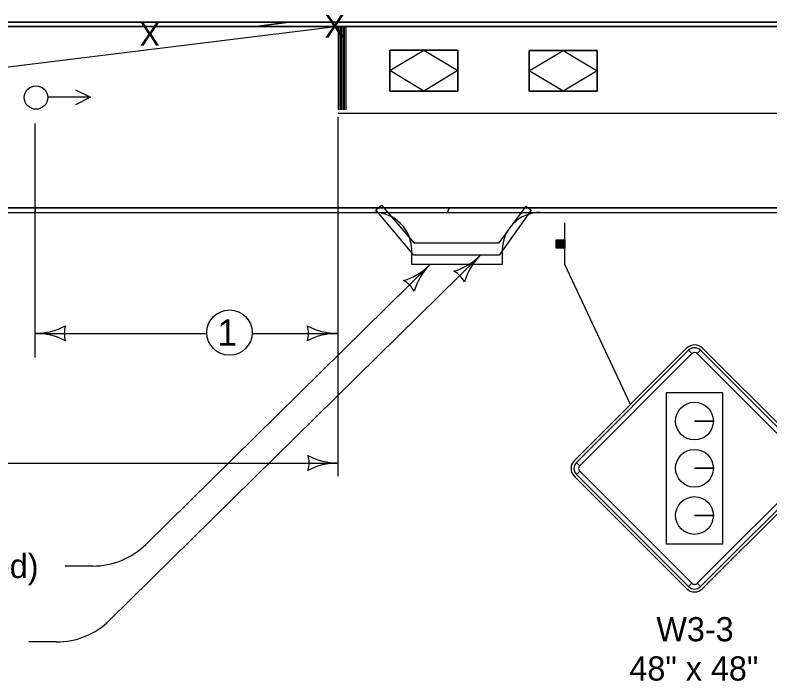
# Model space of a CAD drawing. Extents: x -2134934 to -2119606, y -2139046 to -2137036.
# Drawn here: x -2132728.3 to -2132228.7, y -2137978.4 to -2137537.5 of the extents above; entities that cross this region are included whole.
import ezdxf

# ---------------------------------------------------------------- set-up
doc = ezdxf.new("R2010")
doc.units = 0
for name, color, linetype in [('Default', 7, 'Continuous'), ('dsnCellElements', 7, 'Continuous'), ('dsnStdLabel', 7, 'Continuous'), ('dsnStdLineWork', 7, 'Continuous'), ('Level 2', 7, 'Continuous'), ('Level 4', 7, 'Continuous')]:
    doc.layers.add(name, color=color, linetype=linetype)

msp = doc.modelspace()

# ---------------------------------------------------------------- linework, layer by layer
at = {"layer": 'Default'}
for p, q in [((-2132489.5, -2137666.4), (-2132485.76, -2137663.39)), ((-2132464.31, -2137696.46), (-2132489.5, -2137666.4)), ((-2132485.76, -2137663.39), (-2132464.33, -2137688.36)), ((-2132407.87, -2137688.4), (-2132390.13, -2137664.13)), ((-2132390.13, -2137664.13), (-2132386.63, -2137666.69)), ((-2132386.63, -2137666.69), (-2132407.85, -2137696.47)), ((-2132464.33, -2137688.36), (-2132407.87, -2137688.4)), ((-2132407.85, -2137696.47), (-2132464.31, -2137696.46))]:
    msp.add_line(p, q, dxfattribs=at)
at = {"layer": 'dsnCellElements'}
for centre, radius, start, end in [((-2132450.52, -2137666.56), 42.5, 287.1972, 315.2696), ((-2132390.14, -2137726.38), 42.5, 135.2696, 163.3421), ((-2132483.78, -2137672.74), 42.5, 287.1972, 315.2696), ((-2132483.78, -2137672.74), 42.5, 287.1972, 315.2696), ((-2132423.4, -2137732.56), 42.5, 135.2696, 163.3421), ((-2132423.4, -2137732.56), 42.5, 135.2696, 163.3421), ((-2132445.41, -2137721.79), 16.42, 27.5363, 63.003), ((-2132478.67, -2137727.96), 16.42, 27.5363, 63.003), ((-2132478.67, -2137727.96), 16.42, 27.5363, 63.003), ((-2132550.08, -2137834.09), 16.42, 342.2666, 17.7333), ((-2132514.45, -2137791.59), 42.5, 241.9275, 270), ((-2132514.45, -2137876.59), 42.5, 90, 118.0725)]:
    msp.add_arc(centre, radius, start, end, dxfattribs=at)
at = {"layer": 'dsnStdLabel'}
for p, q in [((-2132283.85, -2137758.12), (-2132358.09, -2137832.37)), ((-2132282.52, -2137759.45), (-2132280.31, -2137761.66)), ((-2132276.78, -2137761.66), (-2132274.57, -2137759.45)), ((-2132198.99, -2137832.37), (-2132273.24, -2137758.12)), ((-2132266.14, -2137806.34), (-2132278.64, -2137806.34)), ((-2132278.64, -2137806.34), (-2132266.14, -2137806.34)), ((-2132354.56, -2137835.9), (-2132356.77, -2137833.69)), ((-2132356.77, -2137841.65), (-2132354.56, -2137839.44)), ((-2132266.14, -2137837.59), (-2132278.64, -2137837.59)), ((-2132278.64, -2137837.59), (-2132266.14, -2137837.59)), ((-2132358.09, -2137842.98), (-2132283.85, -2137917.22)), ((-2132273.24, -2137917.22), (-2132198.99, -2137842.98)), ((-2132266.14, -2137868.84), (-2132278.64, -2137868.84)), ((-2132278.64, -2137868.84), (-2132266.14, -2137868.84)), ((-2132280.31, -2137913.69), (-2132282.52, -2137915.9)), ((-2132274.57, -2137915.9), (-2132276.78, -2137913.69))]:
    msp.add_line(p, q, dxfattribs=at)
for points in [[(-2132282.52, -2137759.45), (-2132356.77, -2137833.69), (-2132354.56, -2137835.9), (-2132280.31, -2137761.66), (-2132282.52, -2137759.45)], [(-2132200.32, -2137833.69), (-2132274.57, -2137759.45), (-2132276.78, -2137761.66), (-2132202.53, -2137835.9), (-2132200.32, -2137833.69)], [(-2132259.81, -2137787.73), (-2132297.28, -2137787.73), (-2132297.28, -2137887.62), (-2132259.81, -2137887.62), (-2132259.81, -2137787.73)], [(-2132356.77, -2137841.65), (-2132282.52, -2137915.9), (-2132280.31, -2137913.69), (-2132354.56, -2137839.44), (-2132356.77, -2137841.65)], [(-2132274.57, -2137915.9), (-2132200.32, -2137841.65), (-2132202.53, -2137839.44), (-2132276.78, -2137913.69), (-2132274.57, -2137915.9)]]:
    msp.add_lwpolyline(points, close=True, dxfattribs=at)
for centre in [(-2132278.64, -2137806.34), (-2132278.64, -2137837.59), (-2132278.64, -2137868.84)]:
    msp.add_circle(centre, 12.5, dxfattribs=at)
for centre, radius, start, end in [((-2132278.54, -2137763.43), 7.5, 45, 134.9997), ((-2132278.54, -2137763.43), 5.62, 45, 134.9997), ((-2132278.54, -2137763.43), 2.5, 45, 134.9997), ((-2132352.79, -2137837.67), 7.5, 134.9997, 225), ((-2132352.79, -2137837.67), 5.62, 134.9997, 225), ((-2132352.79, -2137837.67), 2.5, 134.9997, 225), ((-2132278.54, -2137911.92), 5.62, 225, 315.0002), ((-2132278.54, -2137911.92), 2.5, 225, 315.0002), ((-2132278.54, -2137911.92), 7.5, 225, 315.0002)]:
    msp.add_arc(centre, radius, start, end, dxfattribs=at)
at = {"layer": 'dsnStdLineWork'}
for p, q in [((-2132861.64, -2137545.16), (-2132568.69, -2137545.16)), ((-2132547.01, -2137542.16), (-2132860.67, -2137542.16)), ((-2132547.01, -2137542.16), (-2132568.69, -2137545.16)), ((-2132568.69, -2137545.16), (-2132547.01, -2137542.16)), ((-2132568.69, -2137545.16), (-2132514.45, -2137545.16)), ((-2131861.99, -2137542.16), (-2132547.01, -2137542.16)), ((-2132509.45, -2137545.16), (-2131861.99, -2137545.16)), ((-2131861.95, -2137602.66), (-2132514.45, -2137602.66)), ((-2133364.44, -2137665.16), (-2131861.99, -2137665.16)), ((-2133364.44, -2137665.16), (-2131861.99, -2137665.16)), ((-2132714.94, -2137665.16), (-2132748.32, -2137665.16)), ((-2132714.94, -2137668.16), (-2132714.94, -2137665.16)), ((-2132441.05, -2137665.16), (-2132714.94, -2137665.16)), ((-2132714.94, -2137665.16), (-2132714.94, -2137668.16)), ((-2132442.06, -2137668.16), (-2132441.05, -2137665.16)), ((-2132441.05, -2137665.16), (-2132442.06, -2137668.16)), ((-2131861.99, -2137665.16), (-2132441.05, -2137665.16)), ((-2133364.44, -2137668.16), (-2131861.99, -2137668.16)), ((-2132748.19, -2137668.16), (-2132714.94, -2137668.16)), ((-2132714.94, -2137668.16), (-2132442.06, -2137668.16)), ((-2132442.06, -2137668.16), (-2131861.99, -2137668.16))]:
    msp.add_line(p, q, dxfattribs=at)
for points in [[(-2133174.44, -2137542.16), (-2131861.99, -2137542.16)], [(-2133174.44, -2137545.16), (-2131861.99, -2137545.16)], [(-2133173.75, -2137545.16), (-2131861.29, -2137545.16)], [(-2132514.45, -2137545.16), (-2132513.45, -2137545.16), (-2132512.45, -2137545.16)], [(-2132512.45, -2137545.16), (-2132511.45, -2137545.16), (-2132510.45, -2137545.16), (-2132509.45, -2137545.16)]]:
    msp.add_lwpolyline(points, dxfattribs=at)
at = {"layer": 'Level 2'}
for p, q in [((-2131861.99, -2137545.16), (-2133174.44, -2137545.16)), ((-2132514.45, -2137545.16), (-2133004.39, -2137605.15)), ((-2132514.45, -2137545.16), (-2132514.45, -2137600.16)), ((-2132513.45, -2137545.16), (-2132513.45, -2137600.16)), ((-2132512.45, -2137545.16), (-2132512.45, -2137600.16)), ((-2132511.45, -2137545.16), (-2132511.45, -2137600.16)), ((-2132510.45, -2137545.16), (-2132510.45, -2137600.16)), ((-2132509.45, -2137545.16), (-2132509.45, -2137600.16)), ((-2132480.28, -2137587.78), (-2132480.28, -2137560.78)), ((-2132480.28, -2137560.78), (-2132435.28, -2137560.78)), ((-2132480.28, -2137587.78), (-2132480.28, -2137560.78)), ((-2132480.28, -2137560.78), (-2132435.28, -2137560.78)), ((-2132435.28, -2137560.78), (-2132480.28, -2137560.78)), ((-2132480.28, -2137560.78), (-2132480.28, -2137587.78)), ((-2132435.28, -2137587.78), (-2132435.28, -2137560.78)), ((-2132435.28, -2137560.78), (-2132435.28, -2137587.78)), ((-2132435.28, -2137587.78), (-2132435.28, -2137560.78)), ((-2132388.09, -2137587.86), (-2132388.09, -2137560.86)), ((-2132388.09, -2137560.86), (-2132343.09, -2137560.86)), ((-2132388.09, -2137587.86), (-2132388.09, -2137560.86)), ((-2132388.09, -2137560.86), (-2132343.09, -2137560.86)), ((-2132343.09, -2137560.86), (-2132388.09, -2137560.86)), ((-2132388.09, -2137560.86), (-2132388.09, -2137587.86)), ((-2132343.09, -2137587.86), (-2132343.09, -2137560.86)), ((-2132343.09, -2137560.86), (-2132343.09, -2137587.86)), ((-2132343.09, -2137587.86), (-2132343.09, -2137560.86)), ((-2132480.28, -2137587.78), (-2132435.28, -2137587.78)), ((-2132435.28, -2137587.78), (-2132480.28, -2137587.78)), ((-2132480.28, -2137587.78), (-2132435.28, -2137587.78)), ((-2132388.09, -2137587.86), (-2132343.09, -2137587.86)), ((-2132343.09, -2137587.86), (-2132388.09, -2137587.86)), ((-2132388.09, -2137587.86), (-2132343.09, -2137587.86)), ((-2132706.71, -2137591.74), (-2132678.77, -2137591.74)), ((-2132514.45, -2137842.77), (-2132514.45, -2137605.16)), ((-2132714.94, -2137764.14), (-2132714.94, -2137609.25)), ((-2133364.44, -2137665.16), (-2131861.99, -2137665.16)), ((-2132490.81, -2137668.16), (-2132380.81, -2137668.16)), ((-2132364.45, -2137702.66), (-2132364.45, -2137675.16)), ((-2132369.77, -2137691.8), (-2132369.77, -2137686.21)), ((-2132369.45, -2137686.21), (-2132369.45, -2137691.8)), ((-2132369.23, -2137691.8), (-2132369.23, -2137686.21)), ((-2132368.91, -2137686.21), (-2132368.91, -2137691.8)), ((-2132368.68, -2137691.8), (-2132368.7, -2137686.21)), ((-2132368.27, -2137686.21), (-2132368.25, -2137691.8)), ((-2132368.05, -2137691.8), (-2132368.05, -2137686.21)), ((-2132367.62, -2137686.21), (-2132367.62, -2137691.8)), ((-2132367.24, -2137691.8), (-2132367.24, -2137686.21)), ((-2132366.92, -2137686.21), (-2132366.9, -2137691.8)), ((-2132366.7, -2137691.8), (-2132366.7, -2137686.21)), ((-2132366.43, -2137686.21), (-2132366.43, -2137691.8)), ((-2132366.1, -2137691.8), (-2132366.1, -2137686.21)), ((-2132365.89, -2137686.21), (-2132365.89, -2137691.8)), ((-2132365.67, -2137691.8), (-2132365.67, -2137686.21)), ((-2132365.4, -2137686.21), (-2132365.4, -2137691.8)), ((-2132365.14, -2137691.8), (-2132365.14, -2137686.21)), ((-2132364.86, -2137686.21), (-2132364.86, -2137691.8)), ((-2132665.76, -2137938.19), (-2132420.33, -2137696.47)), ((-2132641.72, -2137887.94), (-2132453.59, -2137702.65)), ((-2132641.72, -2137887.94), (-2132453.59, -2137702.65)), ((-2132320.97, -2137795.25), (-2132364.45, -2137702.66)), ((-2132714.94, -2137748.23), (-2132601.37, -2137748.23)), ((-2132571.38, -2137748.23), (-2132514.94, -2137748.23)), ((-2132739.17, -2137834.09), (-2132514.45, -2137834.09)), ((-2132676.81, -2137902.31), (-2132695.27, -2137902.31)), ((-2132676.81, -2137902.31), (-2132695.27, -2137902.31)), ((-2132700.84, -2137952.56), (-2132719.3, -2137952.56))]:
    msp.add_line(p, q, dxfattribs=at)
for points in [[(-2132688.4, -2137586.93), (-2132678.4, -2137591.93), (-2132688.4, -2137596.93)], [(-2132405.81, -2137693.16), (-2132405.81, -2137702.65), (-2132465.81, -2137702.65), (-2132465.81, -2137693.16)]]:
    msp.add_lwpolyline(points, dxfattribs=at)
msp.add_lwpolyline([(-2132364.54, -2137686.21), (-2132364.54, -2137691.84), (-2132370.17, -2137691.84), (-2132370.17, -2137686.21)], close=True, dxfattribs=at)
for centre, radius in [((-2132714.45, -2137592.11), 7.74), ((-2132586.38, -2137747.73), 15)]:
    msp.add_circle(centre, radius, dxfattribs=at)
for centre, radius, start, end in [((-2132490.81, -2137693.16), 25, 0, 90), ((-2132380.81, -2137693.16), 25, 90, 180), ((-2132714.94, -2137705.73), 42.5, 270, 298.0725), ((-2132679.3, -2137748.23), 16.42, 162.2666, 197.7334), ((-2132550.57, -2137748.23), 16.42, 342.2666, 17.7333), ((-2132514.94, -2137705.73), 42.5, 241.9275, 270), ((-2132714.94, -2137790.73), 42.5, 61.9275, 90), ((-2132514.94, -2137790.73), 42.5, 90, 118.0725), ((-2132676.81, -2137852.31), 50, 270, 314.5635), ((-2132676.81, -2137852.31), 50, 270, 314.5635), ((-2132700.84, -2137902.56), 50, 270, 314.5635)]:
    msp.add_arc(centre, radius, start, end, dxfattribs=at)
at = {"layer": 'Level 4'}
for points in [[(-2132480.28, -2137574.28), (-2132457.78, -2137560.78), (-2132435.28, -2137574.28), (-2132457.78, -2137587.78)], [(-2132388.09, -2137574.36), (-2132365.59, -2137560.86), (-2132343.09, -2137574.36), (-2132365.59, -2137587.86)]]:
    msp.add_lwpolyline(points, close=True, dxfattribs=at)

# ---------------------------------------------------------------- texts
at = {"layer": 'dsnStdLabel'}
for s, p in [('W3-3', (-2132303.84, -2137952.14)), ('48" x 48"', (-2132321.71, -2137978.14))]:
    msp.add_text(s, height=16, dxfattribs=at).set_placement(p)
at = {"layer": 'Level 2'}
for s, height, p in [('X', 15, (-2132523.45, -2137552.51)), ('1', 17.5, (-2132594.44, -2137756.48)), ('265th Road (To Be Closed)', 16, (-2132973.26, -2137910.31))]:
    msp.add_text(s, height=height, dxfattribs=at).set_placement(p)
msp.add_text('X', height=15, rotation=359.9705, dxfattribs=at).set_placement((-2132645.85, -2137557.84))

doc.saveas('drawing.dxf')
